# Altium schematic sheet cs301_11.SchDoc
size A4
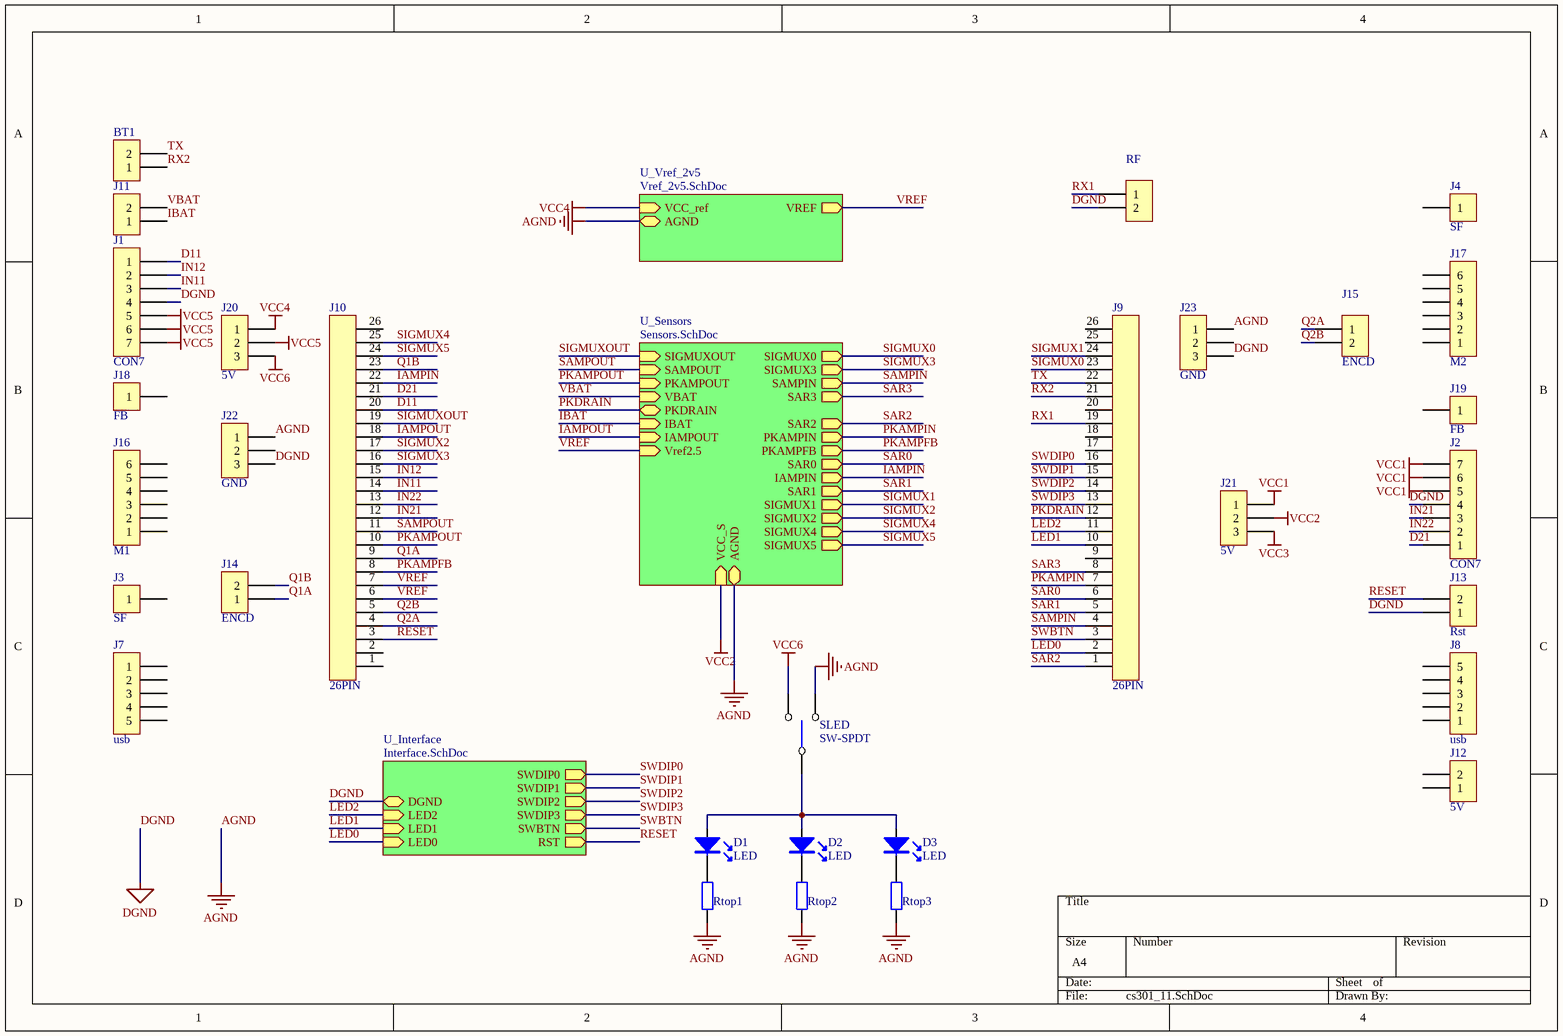
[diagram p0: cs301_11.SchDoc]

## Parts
BT1  Battery  [sip2]  (value not drawn)
D1  LED  [LED0.1/5MM]
D2  LED  [LED0.1/5MM]
D3  LED  [LED0.1/5MM]
J1  CON7  [SIP7]
J2  CON7  [SIP7]
J3  SF  [SIP1/0.6]
J4  SF  [SIP1/0.6]
J7  usb  [SIP5]
J8  usb  [SIP5]
J9  26PIN  [SIP26]
J10  26PIN  [SIP26]
J11  Battery  [sip2]  (value not drawn)
J12  5V  [sip2]
J13  Rst  [sip2]
J14  ENCD  [sip2]
J15  ENCD  [sip2]
J16  M1  [sip6]
J17  M2  [sip6]
J18  FB  [SIP1/0.6]
J19  FB  [SIP1/0.6]
J20  5V  [sip3]
J21  5V  [sip3]
J22  GND  [sip3]
J23  GND  [sip3]
RF  (no value)  [sip2]
Rtop1  270R  [ECE-RESC1608-0603SM]  (value not drawn)
Rtop2  270R  [ECE-RESC1608-0603SM]  (value not drawn)
Rtop3  270R  [ECE-RESC2012-0805SM]  (value not drawn)
SLED  SW-SPDT  [SW-SPDT]

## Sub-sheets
U_Interface = Interface.SchDoc: SWDIP0 (out), SWDIP1 (out), SWDIP2 (out), SWDIP3 (out), SWBTN (out), DGND (bidir), LED2 (in), LED1 (in), LED0 (in), RST (out)
U_Sensors = Sensors.SchDoc: SIGMUX0 (out), SIGMUX3 (out), SIGMUXOUT (in), SAMPIN (out), SAR3 (out), Vref2.5 (in), SAMPOUT (in), SAR2 (out), PKAMPIN (out), PKAMPOUT (in), PKAMPFB (out), VBAT (in), SAR0 (out), PKDRAIN (bidir), IBAT (in), IAMPIN (out), IAMPOUT (in), SAR1 (out), SIGMUX1 (out), SIGMUX2 (out), SIGMUX4 (out), SIGMUX5 (out), VCC_S (in), AGND (bidir)
U_Vref_2v5 = Vref_2v5.SchDoc: VREF (out), VCC_ref (in), AGND (bidir)

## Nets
AGND: J22.1 J23.1 Rtop1.1 Rtop2.1 Rtop3.1 SLED.3 ; sheet U_Sensors/AGND, sheet U_Vref_2v5/AGND
DGND: J1.4 J2.4 J13.1 J22.3 J23.3 RF.2 ; sheet U_Interface/DGND
VCC1: J2.5 J2.6 J2.7 J21.1
VCC2: J21.2 ; sheet U_Sensors/VCC_S
VCC3: J21.3
VCC4: J20.1 ; sheet U_Vref_2v5/VCC_ref
VCC5: J1.5 J1.6 J1.7 J20.2
VCC6: J20.3 SLED.1
D11: J1.1 J10.20
D21: J2.1 J10.21
IAMPIN: J10.22 ; sheet U_Sensors/IAMPIN
IAMPOUT: J10.18 ; sheet U_Sensors/IAMPOUT
IBAT: J11.1 ; sheet U_Sensors/IBAT
IN11: J1.3 J10.14
IN12: J1.2 J10.15
IN21: J2.3 J10.12
IN22: J2.2 J10.13
LED0: J9.2 ; sheet U_Interface/LED0
LED1: J9.10 ; sheet U_Interface/LED1
LED2: J9.11 ; sheet U_Interface/LED2
PKAMPFB: J10.8 ; sheet U_Sensors/PKAMPFB
PKAMPIN: J9.7 ; sheet U_Sensors/PKAMPIN
PKAMPOUT: J10.10 ; sheet U_Sensors/PKAMPOUT
PKDRAIN: J9.12 ; sheet U_Sensors/PKDRAIN
Q1A: J10.9 J14.1
Q1B: J10.23 J14.2
Q2A: J10.4 J15.1
Q2B: J10.5 J15.2
RESET: J10.3 J13.2 ; sheet U_Interface/RST
RX1: J9.19 RF.1
RX2: BT1.1 J9.21
SAMPIN: J9.4 ; sheet U_Sensors/SAMPIN
SAMPOUT: J10.11 ; sheet U_Sensors/SAMPOUT
SAR0: J9.6 ; sheet U_Sensors/SAR0
SAR1: J9.5 ; sheet U_Sensors/SAR1
SAR2: J9.1 ; sheet U_Sensors/SAR2
SAR3: J9.8 ; sheet U_Sensors/SAR3
SIGMUX0: J9.23 ; sheet U_Sensors/SIGMUX0
SIGMUX1: J9.24 ; sheet U_Sensors/SIGMUX1
SIGMUX2: J10.17 ; sheet U_Sensors/SIGMUX2
SIGMUX3: J10.16 ; sheet U_Sensors/SIGMUX3
SIGMUX4: J10.25 ; sheet U_Sensors/SIGMUX4
SIGMUX5: J10.24 ; sheet U_Sensors/SIGMUX5
SIGMUXOUT: J10.19 ; sheet U_Sensors/SIGMUXOUT
SWBTN: J9.3 ; sheet U_Interface/SWBTN
SWDIP0: J9.16 ; sheet U_Interface/SWDIP0
SWDIP1: J9.15 ; sheet U_Interface/SWDIP1
SWDIP2: J9.14 ; sheet U_Interface/SWDIP2
SWDIP3: J9.13 ; sheet U_Interface/SWDIP3
TX: BT1.2 J9.22
VBAT: J11.2 ; sheet U_Sensors/VBAT
VREF: J10.6 J10.7 ; sheet U_Sensors/Vref2.5, sheet U_Vref_2v5/VREF
NetD1_A: D1.A D2.A D3.A SLED.2
NetD1_K: D1.K Rtop1.2
NetD2_K: D2.K Rtop2.2
NetD3_K: D3.K Rtop3.2

Not connected (* = marked no-connect by the designer): J3 1; J4 1; J7 1 2 3 4 5; J8 1 2 3 4 5; J9 9 17 18 20 25 26; J10 1 2 26; J12 1 2; J16 1 2 3 4 5 6; J17 1 2 3 4 5 6; J18 1; J19 1; J22 2; J23 2

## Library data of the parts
BT1 J11-J15 RF = CON2: Connector
J1 J2 = CON7: Connector
J3 J4 J18 J19 = CON1: Connector
J7 J8 = CON5: Connector
J16 J17 = CON6: Connector
J20-J23 = CON3: Connector
Rtop1 Rtop2 = RES000131: RES CER 270R 1608 SM; Assembly Method: Surface Mount; Voltage/Current: 1/10W; Item Type: Item; Path: ece/ts/Lists/Stock Inventory
Rtop3 = RES000531: RES CER 270R 2012 SM; Assembly Method: Surface Mount; Voltage/Current: 1/8W; Item Type: Item; Path: ece/ts/Lists/Stock Inventory
SLED = SW-SPDT: Toggle Switch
